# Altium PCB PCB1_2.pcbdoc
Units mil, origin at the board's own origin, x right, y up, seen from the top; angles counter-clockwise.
Board outline 3649.61 x 3287.5 mil, 2 copper layers (Top Layer, Bottom Layer); 28 components, 46 nets, 138 pads, 14 vias.
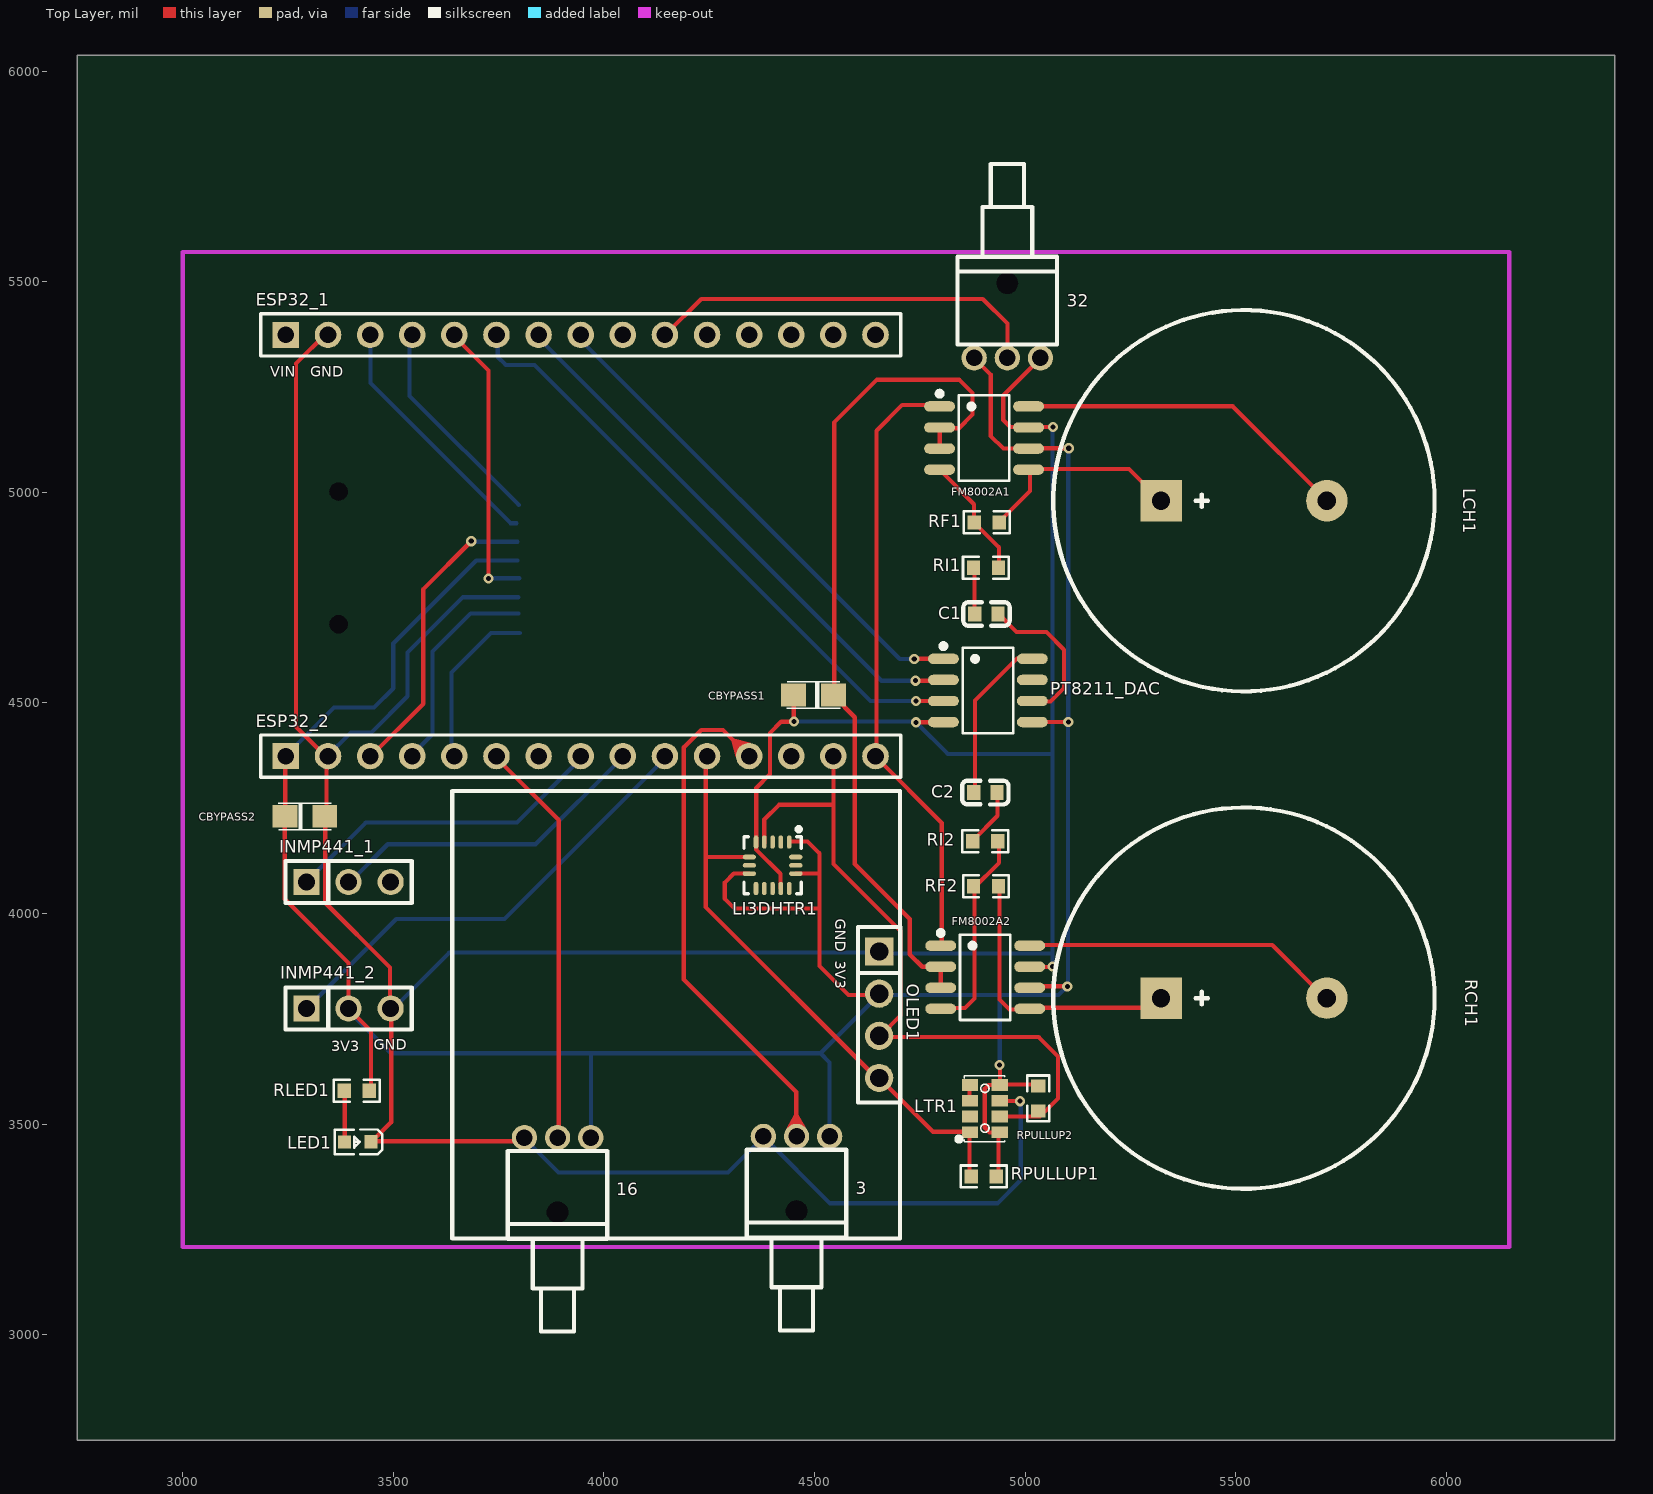
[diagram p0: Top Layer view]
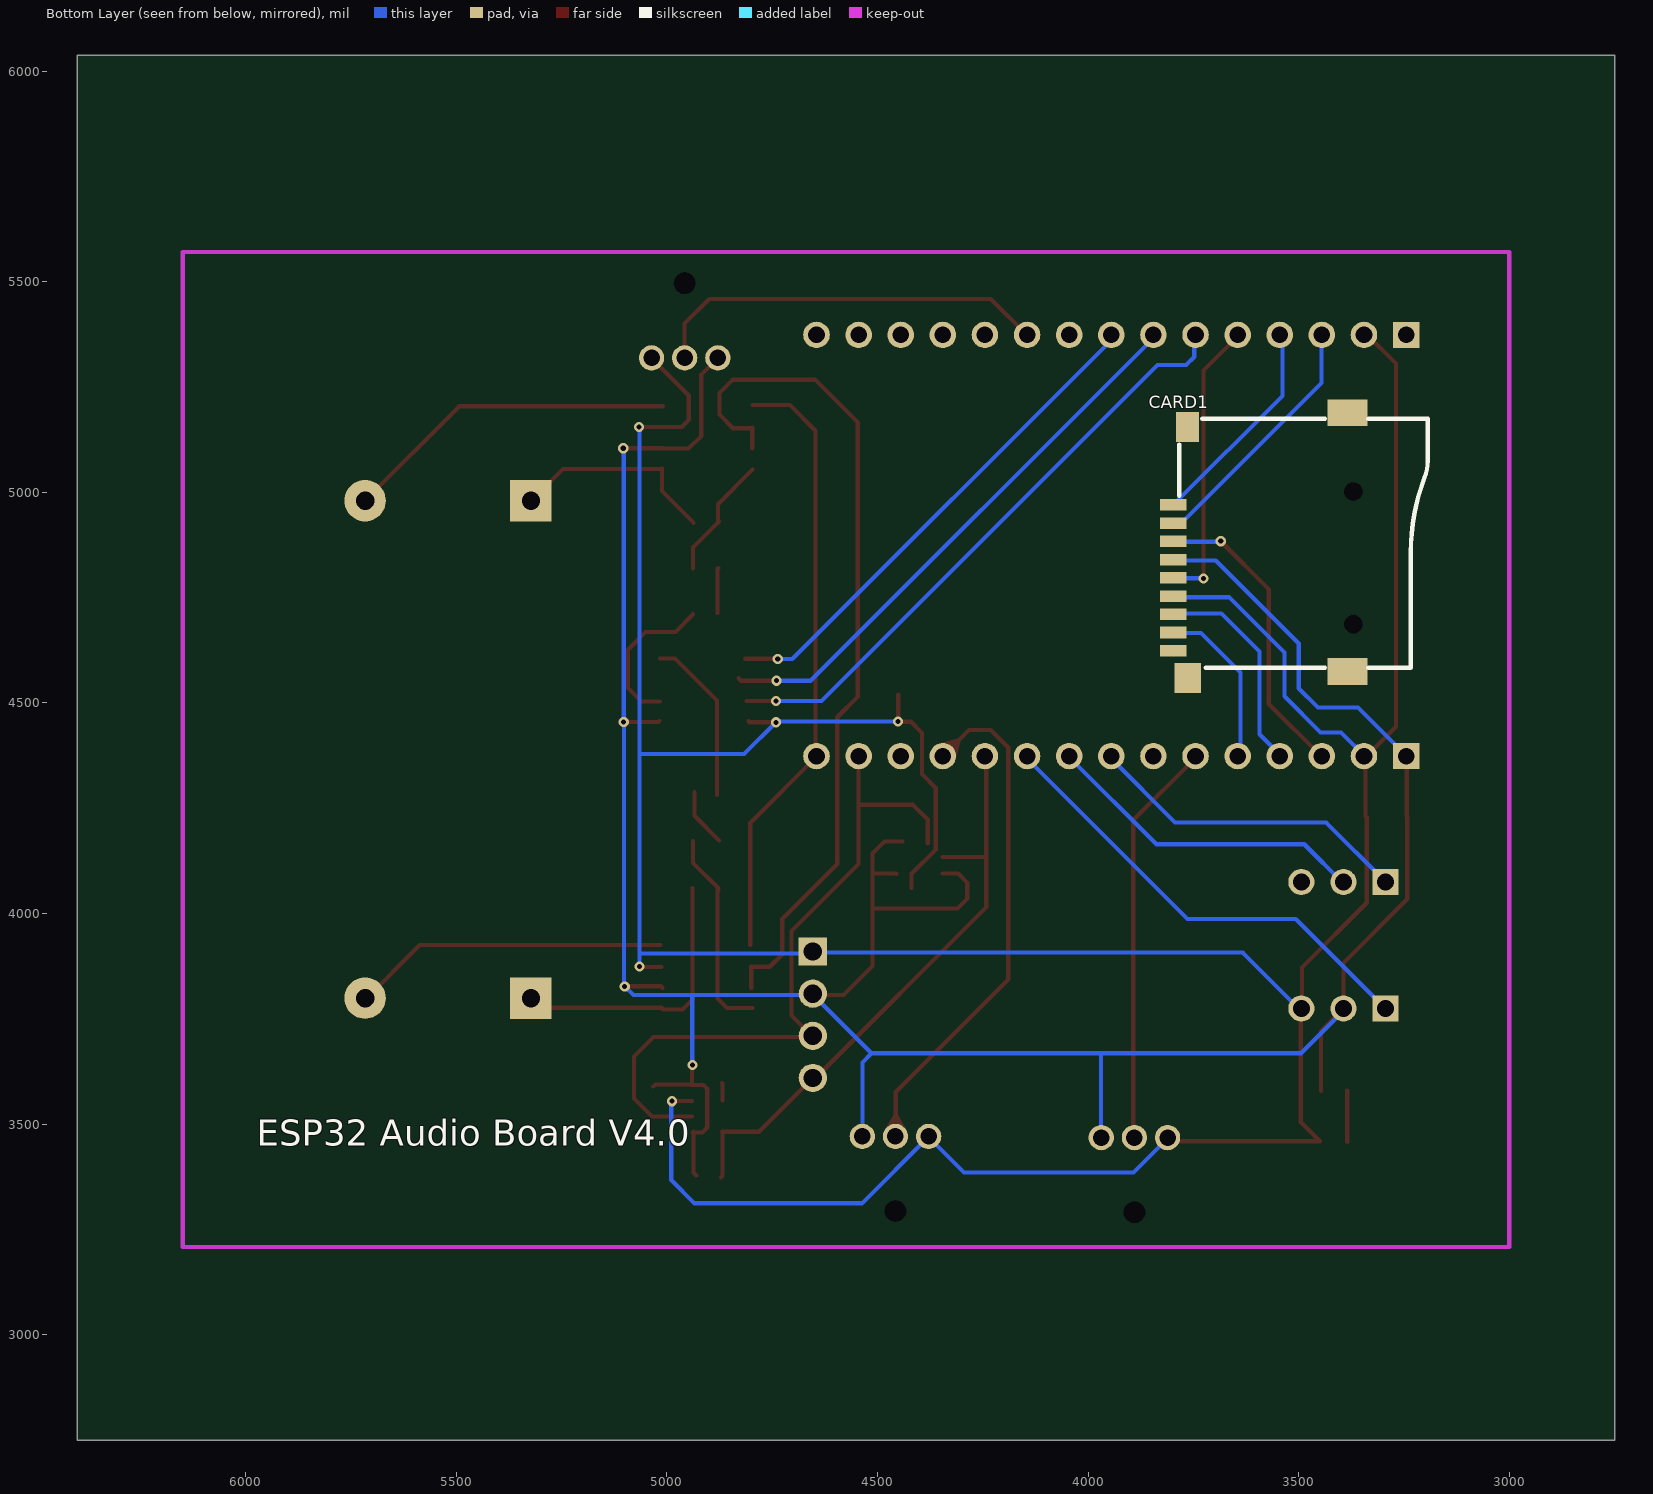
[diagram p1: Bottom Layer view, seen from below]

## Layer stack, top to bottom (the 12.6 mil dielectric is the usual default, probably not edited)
Top Layer: signal copper (thickness not stored)
Dielectric: dielectric 12.6, FR-4, Dk 4.8
Bottom Layer: signal copper (thickness not stored)

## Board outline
6399.61,2750 2750,2750 2750,6037.5 6399.61,6037.5

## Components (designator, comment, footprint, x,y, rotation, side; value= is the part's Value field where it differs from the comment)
3 "={Manufacturer Part}" SW-TH_XKB5858-Z-C 4457.38,3470.93 r180 top
16 "={Manufacturer Part}" SW-TH_XKB5858-Z-C 3889.97,3467.93 r180 top
32 "={Manufacturer Part}" SW-TH_XKB5858-Z-C 4957.77,5319.56 r0 top
C1 "GCM188R71C394KA55D" C0603 4908.13,4711.45 r180 top
C2 "GCM188R71C394KA55D" C0603 4906.01,4287.21 r0 top
CARD1 "={Manufacturer Part}" TF-SMD_TF-15-15 3590.55,4873.98 r180 bottom
CBYPASS1 "TAJA105K016RNJ" CASE-A_3216 4497.69,4518.99 r180 top
CBYPASS2 "TAJA105K016RNJ" CASE-A_3216 3290,4230.83 r0 top
ESP32_1 "={Manufacturer Part}" HDR-TH_15P-P2.54-V-F-1 3944.88,5373.98 r0 top
ESP32_2 "={Manufacturer Part}" HDR-TH_15P-P2.54-V-F-1 3944.88,4373.98 r0 top
FM8002A1 "={Manufacturer Part}" SOP-8_L4.9-W3.9-P1.27-LS6.0-BL 4902.79,5129.16 r270 top
FM8002A2 "={Manufacturer Part}" SOP-8_L4.9-W3.9-P1.27-LS6.0-BL 4905.36,3848.74 r270 top
INMP441_1 "={Manufacturer Part}" HDR-TH_3P-P2.54-V-F 3393.7,4074.77 r0 top
INMP441_2 "={Manufacturer Part}" HDR-TH_3P-P2.54-V-F 3393.7,3774.77 r0 top
LCH1 "={Manufacturer Part}" SPK-TH_BD23.0-P10.00-D0.8-L-RD 5519.69,4980.28 r0 top
LED1 "={Manufacturer Part}" LED0603-RD_RED 3415.49,3457.94 r180 top
LI3DHTR1 "={Manufacturer Part}" LGA-16_L3.0-W3.0-P0.50-TL 4400.47,4114.63 r270 top
LTR1 "={Manufacturer Part}" SENSOR-SMD_L3.9-W2.4-P0.95-BL 4904.58,3536.92 r0 top
OLED1 "={Manufacturer Part}" HDR-TH_4P-P2.54-V-F 4653.54,3759.81 r270 top
PT8211_DAC "={Symbol}" SOP-8_L4.9-W3.9-P1.27-LS6.0-BL 4911.57,4529.77 r270 top
RCH1 "={Manufacturer Part}" SPK-TH_BD23.0-P10.00-D0.8-L-RD 5519.69,3799.18 r0 top
RF1 "Res_0603" R0603 4908.68,4928.76 r0 top
RF2 "Res_0603" R0603 4907.22,4065 r0 top
RI1 "Res_0603" R0603 4907.13,4820.87 r0 top
RI2 "Res_0603" R0603 4905.79,4171.9 r0 top
RLED1 "Res_0603" R0603 3413.38,3579.45 r0 top
RPULLUP1 "Res_0603" R0603 4902.17,3375.8 r0 top
RPULLUP2 "Res_0603" R0603 5031.3,3560.98 r90 top

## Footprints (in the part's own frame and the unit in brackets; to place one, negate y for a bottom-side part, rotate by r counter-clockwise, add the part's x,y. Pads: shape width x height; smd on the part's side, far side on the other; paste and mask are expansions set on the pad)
C0603 [mm]
  rect 0.8x0.9 smd paste+0 mask+0.051: 1(-0.7,0) 2(0.7,0)
  silkscreen extent -1.41,-0.71 1.39,0.72
CASE-A_3216 [mil]
  rect 59.05x53.5 smd paste+0 mask+2: 1(-47.24,0) 2(47.24,0)
  silkscreen extent -63,-32 63,32
HDR-TH_3P-P2.54-V-F [mil]
  rect 62x62 hole 40.16 paste+0 mask+2: 1(-100,0)
  round 62 hole 40.16 paste+0 mask+2: 2(0,0) 3(100,0)
  silkscreen extent -150,-50 150,50
HDR-TH_4P-P2.54-V-F [mm]
  rect 1.7x1.7 hole 1.1 paste+0 mask+0.051: 1(-3.81,0)
  round 1.7 hole 1.1 paste+0 mask+0.051: 2(-1.27,0) 3(1.27,0) 4(3.81,0)
  silkscreen extent -5.29,-1.27 5.29,1.27
HDR-TH_15P-P2.54-V-F-1 [mm]
  rect 1.6x1.575 hole 1 paste+0 mask+0.051: 1(-17.78,0)
  round 1.6 hole 1 paste+0 mask+0.051: 2(-15.24,0) 3(-12.7,0) 4(-10.16,0) 5(-7.62,0) 6(-5.08,0) 7(-2.54,0) 8(0,0) 9(2.54,0) 10(5.08,0) 11(7.62,0) 12(10.16,0) 13(12.7,0) 14(15.24,0) 15(17.78,0)
  silkscreen extent -19.3,-1.27 19.3,1.27
LED0603-RD_RED [mm]
  rect 0.8x0.8 smd paste+0 mask+0.051: 1(-0.8,-0.003) 2(0.8,0.003)
  silkscreen extent -1.49,-0.75 1.39,0.76
LGA-16_L3.0-W3.0-P0.50-TL [mm]
  oval 0.8x0.28 smd paste+0 mask+0.051: 1(-1.4,1) 2(-1.4,0.5) 3(-1.4,0) 4(-1.4,-0.5) 5(-1.4,-1) 9(1.4,-1) 10(1.4,-0.5) 11(1.4,0) 12(1.4,0.5) 13(1.4,1)
  oval 0.28x0.8 smd paste+0 mask+0.051: 6(-0.5,-1.4) 7(0,-1.4) 8(0.5,-1.4) 14(0.5,1.4) 15(0,1.4) 16(-0.5,1.4)
  silkscreen extent -2.3,-1.72 1.73,1.73
R0603 [mil]
  rect 31.75x34.02 smd paste-3937.01 mask+2: 1(-29.66,0) 2(29.66,0)
  silkscreen extent -55,-26 55,26
SENSOR-SMD_L3.9-W2.4-P0.95-BL [mm]
  rect 0.985x0.72 smd paste+0 mask+0.051: 1(-0.898,-1.425) 2(-0.898,-0.475) 3(-0.898,0.475) 4(-0.898,1.425) 5(0.898,1.425) 6(0.898,0.475) 7(0.898,-0.475) 8(0.898,-1.425)
  silkscreen extent -1.59,-2 1.2,1.99
SOP-8_L4.9-W3.9-P1.27-LS6.0-BL [mm]
  oval 0.63x1.865 smd paste+0 mask+0.051: 1(-1.905,-2.682) 2(-0.635,-2.682) 3(0.635,-2.682) 4(1.905,-2.682) 5(1.905,2.682) 6(0.635,2.682) 7(-0.635,2.682) 8(-1.905,2.682)
  silkscreen extent -2.82,-2.83 2.58,1.52
SPK-TH_BD23.0-P10.00-D0.8-L-RD [mm]
  rect 2.5x2.5 hole 1.1 paste+0 mask+0.051: 1(-5,0)
  round 2.5 hole 1.1 paste+0 mask+0.051: 2(5,0)
  silkscreen extent -11.5,-11.5 11.5,11.5
SW-TH_XKB5858-Z-C [mil]
  round 60 hole 39.37 paste+0 mask+2: 1(78.74,0) 2(0,0) 3(-78.74,0)
  Multi-Layer board cut-out: -25.59,177.16 -23.06,166.06 -15.96,157.15 -5.69,152.21 5.69,152.21 15.96,157.15 23.06,166.06 25.59,177.16 25.59,177.16 23.06,188.26 15.96,197.17 5.69,202.11 -5.69,202.11 -15.96,197.17 -23.06,188.26 -25.59,177.16
  silkscreen extent -118,31 118,461
TF-SMD_TF-15-15 [mil]
  rect 63x27.6 smd paste+0 mask+2: 1(-206.75,96.45) 2(-206.75,53.15) 3(-206.75,9.84) 4(-206.75,-33.47) 5(-206.75,-76.77) 6(-206.75,-120.08) 7(-206.75,-163.39) 8(-206.75,-206.7) 9(-206.75,-250)
  rect 63x70.87 smd paste+0 mask+2: 10(-173.17,-314.96)
  rect 94.49x62.99 smd paste+0 mask+2: 11(206.75,-299.22) 12(206.75,314.96)
  rect 55.1x70.9 smd paste+0 mask+2: 13(-173.15,281.51)
  Multi-Layer board cut-out: 198.88,-187.01 201.02,-177.61 207.03,-170.08 215.71,-165.9 225.35,-165.9 234.03,-170.08 240.04,-177.61 242.18,-187.01 242.18,-187.01 240.04,-196.41 234.03,-203.94 225.35,-208.12 215.71,-208.12 207.03,-203.94 201.02,-196.41 198.88,-187.01
  Multi-Layer board cut-out: 198.88,127.95 201.02,137.35 207.03,144.88 215.71,149.06 225.35,149.06 234.03,144.88 240.04,137.35 242.18,127.95 242.18,127.95 240.04,118.55 234.03,111.02 225.35,106.84 215.71,106.84 207.03,111.02 201.02,118.55 198.88,127.95
  silkscreen extent -193,-290 398,301

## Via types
v1: diameter 24.02, hole 12.01, Top Layer to Bottom Layer, 14 vias

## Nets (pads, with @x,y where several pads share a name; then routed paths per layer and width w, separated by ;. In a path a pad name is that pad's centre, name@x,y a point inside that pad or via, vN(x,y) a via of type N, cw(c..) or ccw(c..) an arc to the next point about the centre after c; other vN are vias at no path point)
2: CARD1.7 ESP32_2.4 | length 509.8
  Bottom Layer w10: ESP32_2.4@3541.95,4374.72 3593.13,4425.9 3593.13,4622.06 3683.6,4712.52 CARD1.7@3796.91,4712.52
3V3: 3.3 16.3 32.3 CARD1.4 CBYPASS2.1 ESP32_2.1 FM8002A1.6 FM8002A2.6 INMP441_2.2 LI3DHTR1.1 LI3DHTR1.8 LI3DHTR1.14 LTR1.5 LTR1.8 OLED1.2 PT8211_DAC.5 RLED1.2 RPULLUP1.2 RPULLUP2.2 | length 7270.5
  Top Layer w10: CBYPASS2.1@3241.37,4229.55 3243.5,4231.68 ESP32_2.1@3243.5,4373.33 ; CBYPASS2.1@3242.05,4229.57 3242.05,4034.48 3393.79,3882.75 INMP441_2.2@3393.79,3774.92 ; INMP441_2.2@3393.79,3774.37 INMP441_2.2@3393.79,3774.92 ; RLED1.2@3447.24,3578.4 3447.24,3721.46 INMP441_2.2@3393.79,3774.92 ; LI3DHTR1.8@4345.27,4095.06 4308.26,4095.06 4287.08,4073.87 4287.08,4035 4309.88,4012.19 4511.66,4012.19 ; LI3DHTR1.1@4440.54,4171.05 4483.62,4171.05 4511.66,4143 4511.66,4094.84 ; LI3DHTR1.14@4455.38,4094.51 4455.71,4094.84 4511.66,4094.84 ; OLED1.2@4655.44,3806.45 4580.89,3806.45 4511.66,3875.67 4511.66,4012.19 ; 32.3@4878.47,5319.92 4918.28,5280.11 4918.28,5134.31 4948.56,5104.03 FM8002A1.6@5009.69,5104.03 ; RPULLUP1.2@4930.52,3378.22 4937.14,3384.85 LTR1.8@4937.14,3480.47 ; LTR1.8@4937.14,3482.84 LTR1.8@4937.14,3480.47 ; LTR1.8@4939.51,3480.47 LTR1.8@4937.14,3480.47 ; LTR1.5@4939.51,3593.13 4913.12,3593.13 4904.48,3584.49 4904.48,3491.36 4915.37,3480.47 LTR1.8@4937.14,3480.47 ; v1(4939.69,3640.25) 4940.31,3639.64 LTR1.5@4940.31,3593.74 ; LTR1.5@4939.73,3593.74 LTR1.5@4940.31,3593.74 ; LTR1.5@4940.31,3593.63 LTR1.5@4940.31,3593.74 ; LTR1.5@4940.76,3594.45 5027.22,3594.45 RPULLUP2.2@5032.27,3589.4 ; FM8002A1.6@5010.23,5105.2 5010.5,5104.93 v1(5103.73,5104.93) ; FM8002A2.6@5010.49,3824.1 5013.69,3827.3 v1@5100.24,3827.3 ; PT8211_DAC.5@5017.98,4457.05 5019.91,4455.12 v1(5102.61,4455.12) ; 4511.66,4012.19 4511.66,4094.84
  Bottom Layer w10: ESP32_2.1@3243.95,4374.4 3358.83,4489.29 3454.21,4489.29 3499.73,4534.81 3499.73,4641.02 3696.98,4838.28 CARD1.4@3794.53,4838.28 ; INMP441_2.2@3390.7,3772.36 3494.74,3668.32 3969.32,3668.32 ; 16.3@3969.32,3466.53 3969.32,3668.32 ; 3.3@4535.66,3472.17 4535.66,3646.72 4514.07,3668.32 ; OLED1.2@4653.88,3808.13 4514.07,3668.32 ; OLED1.2@4654.05,3806.35 5079.35,3806.35 v1(5100.27,3827.27) 5101.96,3828.96 5101.96,4454.47 v1(5102.61,4455.12) 5102.61,5103.81 v1(5103.73,5104.93) ; v1(4939.69,3640.25) 4939.69,3804.67 ; 3969.32,3668.32 4514.07,3668.32
4: CARD1.8 ESP32_2.5 | length 401.7
  Bottom Layer w10: ESP32_2.5@3642.52,4373.17 3642.52,4382.92 3638.19,4387.26 3638.19,4572.35 3732,4666.16 CARD1.8@3800.04,4666.16
5: ESP32_2.8 INMP441_1.1 | length 771.1
  Bottom Layer w10: INMP441_1.1@3295.97,4077.84 3434.7,4216.56 3793.44,4216.56 ESP32_2.8@3946.26,4369.38
12: CARD1.1 ESP32_1.4 | length 514.6
  Bottom Layer w10: ESP32_1.4@3538.61,5377.05 3538.61,5229.26 CARD1.1@3797.97,4969.9
13: CARD1.2 ESP32_1.3 | length 596.3
  Bottom Layer w10: ESP32_1.3@3445.67,5371.36 3445.67,5259.68 3778.35,4927 CARD1.2@3792.49,4927
14: CARD1.5 ESP32_1.5 | length 684.5
  Top Layer w10: ESP32_1.5@3643.23,5372.42 3726.22,5289.43 v1(3726.22,4795.58)
  Bottom Layer w10: v1(3726.22,4795.58) 3726.94,4796.3 CARD1.5@3799.2,4796.3
15: CARD1.3 ESP32_2.3 | length 720.6
  Top Layer w10: ESP32_2.3@3446.11,4372.95 3571.24,4498.08 3571.24,4770.33 v1(3685.04,4884.14)
  Bottom Layer w10: v1(3685.04,4884.14) 3686.45,4882.72 CARD1.3@3794.95,4882.72
18: ESP32_2.9 INMP441_1.2 | length 774.2
  Bottom Layer w10: INMP441_1.2@3393.52,4071.33 3486.72,4164.54 3837.88,4164.54 ESP32_2.9@4043.8,4370.47
19: ESP32_2.10 INMP441_2.1 | length 1102.9
  Bottom Layer w10: INMP441_2.1@3292.45,3772.74 3507.05,3987.34 3763.91,3987.34 ESP32_2.10@4147.58,4371.01
21: ESP32_2.11 LI3DHTR1.6 LTR1.1 OLED1.4 RPULLUP1.1 | length 1405
  Top Layer w10: ESP32_2.11@4241.59,4366.79 4241.59,4134.14 ; LI3DHTR1.6@4345.24,4134.35 4241.8,4134.35 4241.59,4134.14 ; OLED1.4@4648.97,3607.95 4241.59,4015.33 4241.59,4134.14 ; OLED1.4@4656.78,3606.62 4781.39,3482.01 LTR1.1@4868.37,3482.01 ; LTR1.1@4868.37,3482.72 LTR1.1@4868.37,3482.01 ; LTR1.1@4868.72,3482.01 LTR1.1@4868.37,3482.01 ; RPULLUP1.1@4871.92,3374.09 4868.37,3377.64 LTR1.1@4868.37,3482.01
22: ESP32_2.14 LI3DHTR1.4 LTR1.7 OLED1.3 RPULLUP2.1 | length 1692.6
  Top Layer w10: LI3DHTR1.4@4380.74,4167.1 4380.74,4223.12 4415.85,4258.22 4545.35,4258.22 ; ESP32_2.14@4545.35,4372.18 4545.35,4258.22 ; OLED1.3@4651.85,3705.46 OLED1.3@4653.2,3706.81 ; OLED1.3@4652.36,3709.74 OLED1.3@4656.13,3709.74 ; OLED1.3@4652.66,3706.81 OLED1.3@4653.2,3706.81 ; OLED1.3@4652.99,3707.56 OLED1.3@4653.47,3707.08 ; LTR1.7@4940.93,3518.42 RPULLUP2.1@5035.13,3518.42 ; RPULLUP2.1@5035.6,3518.42 5078.2,3561.02 5078.2,3660.9 5032.29,3706.81 OLED1.3@4653.2,3706.81 ; 4545.35,4258.22 4545.35,4117.64 4704.04,3958.94 4704.04,3757.65 OLED1.3@4656.13,3709.74 ; OLED1.3@4653.2,3706.81 OLED1.3@4653.47,3707.08 ; OLED1.3@4653.47,3707.08 OLED1.3@4656.13,3709.74
23: ESP32_2.15 FM8002A1.1 FM8002A2.1 | length 1458.8
  Top Layer w10: ESP32_2.15@4643.35,4373.98 4802.18,4215.16 FM8002A2.1@4802.18,3925.86 ; ESP32_2.15@4645.46,4376.17 4647.35,4378.06 4647.35,5146.44 4708.17,5207.26 FM8002A1.1@4796.02,5207.26
25: ESP32_1.8 PT8211_DAC.1 | length 1191.6
  Top Layer w10: v1(4736.85,4604.53) 4737.32,4605.01 PT8211_DAC.1@4814.01,4605.01
  Bottom Layer w10: ESP32_1.8@3938.87,5368.13 4702.46,4604.53 v1(4736.85,4604.53)
26: ESP32_1.7 PT8211_DAC.2 | length 1326
  Top Layer w10: v1(4740.16,4552.94) 4823.95,4552.94 PT8211_DAC.2@4829.63,4558.62
  Bottom Layer w10: ESP32_1.7@3843.67,5368.13 4658.87,4552.94 v1(4740.16,4552.94)
27: ESP32_1.6 PT8211_DAC.3 | length 1455.1
  Top Layer w10: v1(4740.64,4504.66) PT8211_DAC.3@4811.17,4504.66
  Bottom Layer w10: ESP32_1.6@3747.93,5375.32 3747.93,5321.98 3767.07,5302.84 3835.06,5302.84 4633.25,4504.66 v1(4740.64,4504.66)
32: 32.2 ESP32_1.10 | length 954.7
  Top Layer w10: ESP32_1.10@4145.39,5373.79 4231.18,5459.58 4899.45,5459.58 4958.2,5400.83 32.2@4958.2,5318.83
33: ESP32_1.9
34: ESP32_1.12
35: ESP32_1.11
$1N1978: INMP441_1.3
$1N2019: PT8211_DAC.7
$1N2635: LED1.2 RLED1.1 | length 121.4
  Top Layer w10: LED1.2@3384.38,3457.74 RLED1.1@3384.38,3579.12
$1N3970: CARD1.9
$1N4896: FM8002A1.4 RF1.1 RI1.2 | length 297.6
  Top Layer w10: FM8002A1.4@4796.54,5054.35 4878.97,4971.92 RF1.1@4878.97,4928.5 ; RF1.1@4876.49,4930.98 RF1.1@4878.97,4928.5 ; RF1.1@4878.97,4927.34 RF1.1@4878.97,4928.5 ; RI1.2@4937.89,4819.95 4937.89,4869.58 RF1.1@4878.97,4928.5
$1N5217: FM8002A2.4 RF2.1 RI2.2 | length 493
  Top Layer w10: FM8002A2.4@4796.85,3775.63 4857.31,3775.63 4879.92,3798.24 RF2.1@4879.92,4057.51 ; RF2.1@4877.63,4060.24 4937.91,4120.51 RI2.2@4937.91,4171.63 ; RF2.1@4877.75,4055.42 4879.88,4057.55 RF2.1@4878.5,4058.93
$1N11477: C1.2 RI1.1 | length 107.5
  Top Layer w10: RI1.1@4878.17,4820.79 4879.85,4819.11 C1.2@4879.85,4713.97
$1N11500: C2.2 RI2.1 | length 138.9
  Top Layer w10: RI2.1@4876.17,4173.66 4934.86,4232.36 C2.2@4934.86,4288.21
$2N305: LTR1.3 LTR1.4 | length 41.5
  Top Layer w10: LTR1.3@4868.37,3555.86 4868.37,3596.33 LTR1.4@4869.08,3597.04
EN: ESP32_1.15
GND: 3.1 16.1 32.1 CARD1.6 CBYPASS1.2 CBYPASS2.2 ESP32_1.2 ESP32_2.2 FM8002A1.7 FM8002A2.7 INMP441_2.3 LED1.1 LI3DHTR1.5 LI3DHTR1.12 LTR1.6 OLED1.1 PT8211_DAC.4 | length 9224.1
  Top Layer w10: CBYPASS2.2@3338.24,4229.57 3338.24,4025.81 3492.14,3871.91 INMP441_2.3@3492.14,3770.03 ; CBYPASS2.2@3339.36,4228.48 3341.49,4230.61 ESP32_2.2@3341.49,4371.27 ; ESP32_2.2@3341.49,4376.52 ESP32_2.2@3341.49,4371.27 ; ESP32_1.2@3342.48,5379.14 3269.2,5305.87 3269.2,4443.55 ESP32_2.2@3341.49,4371.27 ; ESP32_2.2@3344.88,4367.87 ESP32_2.2@3341.49,4371.27 ; LED1.1@3449.41,3459.18 LED1.1@3450.98,3460.75 ; LED1.1@3449.6,3460.75 LED1.1@3450.98,3460.75 ; INMP441_2.3@3494.93,3773.49 3494.93,3504.7 LED1.1@3450.98,3460.75 ; 16.1@3824.5,3467.14 3816.69,3459.33 3452.4,3459.33 LED1.1@3450.98,3460.75 ; LI3DHTR1.5@4361.7,4168.56 LI3DHTR1.5@4361.7,4168.7 ; LI3DHTR1.12@4419.37,4060.53 4419.37,4094.43 4361.55,4152.25 LI3DHTR1.5@4361.7,4168.7 ; CBYPASS1.2@4450.61,4519.84 v1@4450.61,4456.97 ; v1(4451.35,4456.22) v1@4450.61,4456.97 ; v1(4741.27,4454.18) 4804.22,4454.18 PT8211_DAC.4@4806.59,4456.54 ; LTR1.6@4940.75,3554.86 4988.03,3554.86 v1(4988.38,3554.51) ; FM8002A1.7@5006.86,5155.11 FM8002A1.7@5007.44,5155.11 ; FM8002A2.7@5013.11,3873.26 5064.28,3873.26 v1(5065.11,3874.09) ; 32.1@5037.35,5318.98 4948.19,5229.83 4948.19,5171.72 4964.85,5155.06 FM8002A1.7@5007.44,5155.11 ; v1(5066.03,5155.18) 5065.96,5155.11 FM8002A1.7@5007.44,5155.11 ; LI3DHTR1.5@4361.7,4168.7 4361.7,4298.44 4394.3,4331.04 4394.3,4429.03 4420.81,4455.53 4449.17,4455.53 v1@4450.61,4456.97
  Bottom Layer w10: ESP32_2.2@3340.41,4371.15 3399.34,4430.08 3447.87,4430.08 3533.93,4516.14 3533.93,4619.95 3665.23,4751.25 CARD1.6@3796.37,4751.25 ; INMP441_2.3@3497.99,3772.36 3632.93,3907.3 OLED1.1@4652.35,3907.3 ; 16.1@3813.36,3466.76 3813.36,3463.92 3892.18,3385.1 4294.41,3385.1 3.1@4378.55,3469.24 ; 3.1@4379.83,3468.95 4536.74,3312.03 4934.36,3312.03 4989.74,3367.42 4989.74,3553.15 v1(4988.38,3554.51) ; v1(4451.35,4456.22) 4739.22,4456.22 v1(4741.27,4454.18) 4816.62,4378.82 5065.11,4378.82 ; OLED1.1@4649.94,3911.06 4649.94,3911.22 OLED1.1@4653.87,3907.3 ; OLED1.1@4654.51,3906.65 OLED1.1@4653.87,3907.29 ; OLED1.1@4654.73,3905.5 5064.24,3905.5 5065.11,3904.63 ; v1(5065.11,3874.09) 5065.11,3904.63 ; v1(5066.03,5155.18) 5065.11,5154.25 5065.11,4378.82 ; OLED1.1@4652.35,3907.3 OLED1.1@4653.87,3907.3 ; OLED1.1@4652.35,3907.3 OLED1.1@4653.87,3907.29 ; 5065.11,3904.63 5065.11,4378.82
LCH: C1.1 PT8211_DAC.6 | length 369.4
  Top Layer w10: C1.1@4937.89,4710.6 4979.95,4668.55 5050.6,4668.55 5092.66,4626.49 5092.66,4535.67 5060.67,4503.68 PT8211_DAC.6@5016.96,4503.68
LCHAMP1: FM8002A1.5 LCH1.1 RF1.2 | length 498.4
  Top Layer w10: RF1.2@4937.01,4928.18 5011.87,5003.04 FM8002A1.5@5011.87,5056.87 ; FM8002A1.5@5013.65,5055.5 5247.07,5055.5 LCH1.1@5321.51,4981.06
LCHAMP2: FM8002A1.8 LCH1.2 | length 802.6
  Top Layer w10: FM8002A1.8@5009.87,5204.38 5493.1,5204.38 LCH1.2@5718.94,4978.54
RCH: C2.1 PT8211_DAC.8 | length 400.3
  Top Layer w10: C2.1@4881.01,4282.34 4881.01,4505.69 4980.73,4605.4 PT8211_DAC.8@5016.63,4605.4
RCHAMP1: FM8002A2.5 RCH1.1 RF2.2 | length 662.7
  Top Layer w10: RF2.2@4939.51,4061.01 4939.51,3796.16 4963.18,3772.5 5008.62,3772.5 FM8002A2.5@5010.04,3773.92 ; FM8002A2.5@5012.83,3776.45 5298.71,3776.45 RCH1.1@5320.68,3798.41
RCHAMP2: FM8002A2.8 RCH1.2 | length 755.7
  Top Layer w10: FM8002A2.8@5015.01,3925.15 5586.94,3925.15 RCH1.2@5716.88,3795.22
RX0: 3.2 ESP32_2.12 | length 1232.8
  Top Layer w10: ESP32_2.12@4345.92,4373.04 4282.74,4436.21 4230.97,4436.21 4189.5,4394.75 4189.5,3843.68 4456.76,3576.41 4456.76,3474.22 3.2@4458.02,3472.95
RX2: 16.2 ESP32_2.6 | length 954.9
  Top Layer w10: ESP32_2.6@3747.46,4367.2 3892.84,4221.82 16.2@3892.84,3472.55
TX0: ESP32_2.13
TX2: ESP32_2.7
VDD/2: CBYPASS1.1 FM8002A1.2 FM8002A1.3 FM8002A2.2 FM8002A2.3 | length 2041.7
  Top Layer w10: CBYPASS1.1@4546.7,4515.17 4595.69,4466.18 4595.69,4117.91 4726.3,3987.3 4726.3,3903.19 4755.77,3873.72 FM8002A2.2@4800.7,3873.72 ; CBYPASS1.1@4546.72,4520.65 4546.72,5166.01 4648.5,5267.78 4843.5,5267.78 4875.46,5235.82 4875.46,5184.82 4842.91,5152.27 FM8002A1.2@4799.2,5152.27 ; FM8002A1.2@4797.05,5153.78 4797.55,5153.28 FM8002A1.3@4797.55,5104.68 ; FM8002A2.3@4798.93,3823.04 4799.87,3823.98 FM8002A2.2@4799.87,3871.79
VIN: ESP32_1.1
VN: ESP32_1.13
VP: ESP32_1.14
"": CARD1.10 CARD1.11 CARD1.12 CARD1.13 LI3DHTR1.2 LI3DHTR1.3 LI3DHTR1.7 LI3DHTR1.9 LI3DHTR1.10 LI3DHTR1.11 LI3DHTR1.13 LI3DHTR1.15 LI3DHTR1.16 LTR1.2

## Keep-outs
Board Outline Layer:
  lines w10 net "": 3000,3208.63 6149.61,3208.63 6149.61,5570.83 3000,5570.83 3000,3208.63

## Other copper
Top Layer:
  region net RX0: 4346.92,4405.41 4310.61,4415.42 4303.52,4408.36 4313.44,4372.07
  region net RX0: 4479.47,3491.23 4461.76,3522.03 4451.76,3521.83 4434.47,3490.31

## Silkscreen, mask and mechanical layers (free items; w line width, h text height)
Top Silkscreen Layer:
  circle w10 net "": c4842.83,3464.57 r6
  lines w10 net "": 3279.48,4202.62 3279.48,4258.79 ; 4505.86,4490.67 4506.18,4547.16 ; 3640,3228.31 4702.99,3228.31 4702.99,4291.31 3640,4291.31 3640,3228.31
  text "VIN" at 3207.82,5274.57 h25.55
  text "GND" at 3302.82,5274.57 h25.55
  text "GND" at 4548.74,3988.02 h25.55 r270
  text "3V3" at 4548.74,3888.02 h25.55 r270
  text "GND" at 3453.9,3676.5 h25.55
  text "3V3" at 3352.82,3673.24 h25.55
Bottom Silkscreen Layer:
  text "ESP32 Audio Board V4.0" at 5973.71,3448.73 h61.32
